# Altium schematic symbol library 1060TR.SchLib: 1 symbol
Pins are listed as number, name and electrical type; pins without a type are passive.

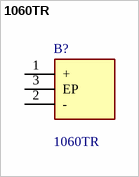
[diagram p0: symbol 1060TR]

## 1060TR
designator B?
Coin Cell Battery Holders 20MM SMT CELL HOLDER; Manufacturer_Name: Keystone Electronics; Geometry.Height: 5.51mm
footprint 1060TR
pins: 1 +, 2 -, 3 EP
